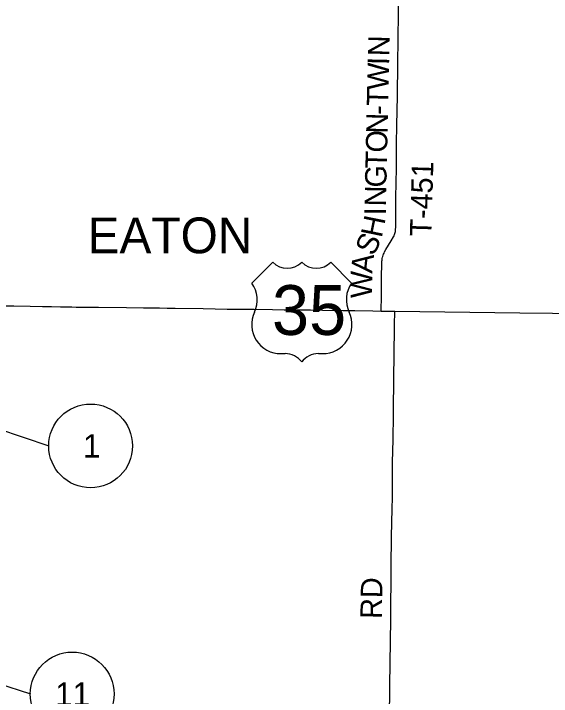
# Model space of a CAD drawing. Extents: x 1341221 to 1914484, y 79347 to 658398.
# Drawn here: x 1399525 to 1414179, y 603681 to 622283 of the extents above; entities that cross this region are included whole.
import ezdxf

# ---------------------------------------------------------------- set-up
doc = ezdxf.new("R2010")
doc.units = 0
for name, color, linetype in [('GM_X_County', 7, 'Continuous'), ('GM_X_County_Road_Text', 7, 'Continuous'), ('GM_X_Major_Lake', 7, 'Continuous'), ('GM_X_Major_River_Text', 7, 'Continuous'), ('GM_X_Township_Text', 7, 'Continuous'), ('GM_X_Unincorporated', 7, 'Continuous'), ('GM_X_Unincorporated_Text', 7, 'Continuous'), ('GM_X_US_Location', 7, 'Continuous')]:
    doc.layers.add(name, color=color, linetype=linetype)

msp = doc.modelspace()

# ---------------------------------------------------------------- linework, layer by layer
at = {"layer": 'GM_X_County'}
msp.add_line((1390836, 606703), (1399981, 603745), dxfattribs=at)
for centre in [(1401623, 610504), (1401121, 603745)]:
    msp.add_circle(centre, 1141, dxfattribs=at)
at = {"layer": 'GM_X_County_Road_Text'}
msp.add_line((1392194, 613303), (1400482, 610504), dxfattribs=at)
at = {"layer": 'GM_X_Township_Text'}
for points in [[(1409929, 616344), (1409934, 616372), (1409936, 616401), (1409939, 616469), (1409941, 616676), (1409945, 617277), (1409955, 618070), (1409962, 618742), (1409971, 619235), (1409985, 620047), (1409998, 620923), (1410005, 621575), (1410016, 622302), (1410025, 622793), (1410037, 623543), (1410048, 624450), (1410047, 624570)], [(1409906, 616264), (1409916, 616292), (1409923, 616318), (1409929, 616344)], [(1409543, 614179), (1409546, 614598), (1409553, 615065), (1409558, 615513), (1409561, 615540), (1409564, 615570), (1409572, 615614), (1409579, 615644), (1409586, 615670), (1409596, 615700), (1409607, 615730), (1409621, 615760), (1409634, 615789), (1409670, 615856), (1409812, 616091), (1409876, 616198), (1409891, 616230), (1409906, 616264)], [(1409776, 603976), (1409803, 605781), (1409818, 607208), (1409827, 608033), (1409839, 608787), (1409846, 609099), (1409853, 610053), (1409865, 610680), (1409873, 611352), (1409890, 612452), (1409896, 612891), (1409905, 613834), (1409912, 614136), (1409912, 614172)], [(1409703, 598728), (1409708, 599187), (1409726, 600620), (1409751, 602148), (1409773, 603779), (1409776, 603976)]]:
    msp.add_lwpolyline(points, dxfattribs=at)
at = {"layer": 'GM_X_Unincorporated'}
for p, q in [((1399527, 614318), (1399972, 614312)), ((1401231, 614289), (1401509, 614286)), ((1401509, 614286), (1401826, 614283)), ((1401826, 614283), (1401837, 614283))]:
    msp.add_line(p, q, dxfattribs=at)
for points in [[(1397357, 614352), (1397695, 614347), (1397830, 614345), (1398213, 614340), (1398263, 614339), (1398322, 614338), (1398603, 614333), (1399083, 614324), (1399360, 614321), (1399421, 614320), (1399527, 614318)], [(1399972, 614312), (1400314, 614304), (1400557, 614299), (1400800, 614296), (1401107, 614290), (1401231, 614289)], [(1401837, 614283), (1402602, 614276), (1403062, 614270), (1403273, 614266), (1403504, 614264), (1403708, 614261), (1403926, 614258), (1404687, 614249), (1405340, 614235), (1405704, 614231), (1406082, 614226), (1406581, 614218), (1406894, 614213), (1407611, 614208), (1407944, 614204), (1408494, 614195), (1408820, 614191), (1409313, 614185), (1409543, 614179), (1409912, 614172)], [(1409912, 614172), (1410597, 614163), (1413316, 614135), (1414209, 614122), (1414730, 614114), (1416201, 614093), (1417629, 614076), (1417647, 614076), (1418090, 614071), (1418515, 614067), (1419201, 614060), (1419803, 614052), (1419866, 614051), (1420908, 614038), (1423200, 614008), (1423652, 614002), (1425088, 613986), (1426031, 613975), (1428365, 613945), (1430084, 613922), (1432126, 613895), (1433092, 613879), (1434871, 613851), (1435308, 613844)]]:
    msp.add_lwpolyline(points, dxfattribs=at)
at = {"layer": 'GM_X_Unincorporated_Text'}
for p, q in [((1406585, 615507), (1406020, 614942)), ((1408734, 614942), (1408169, 615507)), ((1406811, 613019), (1406924, 613019)), ((1407829, 613019), (1407942, 613019))]:
    msp.add_line(p, q, dxfattribs=at)
for centre, radius, start, end in [((1406981, 615911), 566, 225.573, 314.427), ((1407773, 615911), 566, 225.573, 314.427), ((1405371, 614488), 792, 334.5471, 35.0009), ((1409383, 614488), 792, 144.9991, 205.4529), ((1406803, 613811), 792, 154.8319, 270.6383), ((1407951, 613811), 792, 269.3617, 25.1681), ((1406924, 612453), 566, 36.8699, 90), ((1407829, 612453), 566, 90, 143.1301)]:
    msp.add_arc(centre, radius, start, end, dxfattribs=at)

# ---------------------------------------------------------------- texts
at = {"layer": 'GM_X_County'}
for s, height, p in [('1', 639, (1401414, 610185)), ('11', 638.8, (1400657, 603425))]:
    msp.add_text(s, height=height, dxfattribs=at).set_placement(p)
at = {"layer": 'GM_X_Major_Lake'}
for s in ['0', '/']:
    msp.add_text(s, height=1.95, dxfattribs=at).set_placement((1407376, 614196))
msp.add_text('35', height=1.95, rotation=0, dxfattribs=at).set_placement((1406974, 613792))
at = {"layer": 'GM_X_Major_River_Text'}
for s, rotation, p in [('N', 88.7231, (1409762, 621118)), ('W', 88.7231, (1409742, 620200)), ('I', 88.7236, (1409757, 620878)), ('T', 88.7228, (1409732, 619762)), ('-', 88.7236, (1409727, 619522)), ('N', 88.7231, (1409715, 619008)), ('O', 88.7231, (1409704, 618493)), ('T', 88.7228, (1409694, 618055)), ('T-451', 88.3151, (1410906, 616205)), ('G', 88.7231, (1409682, 617541)), ('N', 88.7249, (1409671, 617026)), ('I', 89.9651, (1409671, 616789)), ('H', 78.4866, (1409555, 616158)), ('S', 64.4571, (1409336, 615654)), ('A', 84.123, (1409297, 615192)), ('W', 89.4743, (1409292, 614529)), ('RD', 89.0118, (1409558, 605788))]:
    msp.add_text(s, height=585, rotation=rotation, dxfattribs=at).set_placement(p)
at = {"layer": 'GM_X_Unincorporated_Text'}
msp.add_text('35', height=1357.4, dxfattribs=at).set_placement((1406567, 613528))
at = {"layer": 'GM_X_US_Location'}
msp.add_text('EATON', height=975, rotation=0, dxfattribs=at).set_placement((1401540, 615753))

doc.saveas('drawing.dxf')
